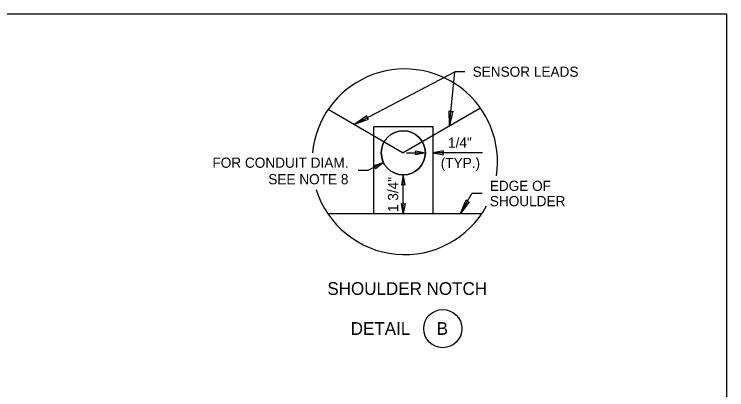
# Model space of a CAD drawing. Extents: x 99862 to 103151, y 100000 to 105076.
# Drawn here: x 102031 to 103151, y 104485 to 105076 of the extents above; entities that cross this region are included whole.
import ezdxf

# ---------------------------------------------------------------- set-up
doc = ezdxf.new("R2010")
doc.units = 0
for name, color, linetype in [('Level 1', 7, 'Continuous'), ('Level 15', 7, 'Continuous'), ('Level 18', 7, 'Continuous'), ('Level 20', 7, 'Continuous'), ('Level 22', 7, 'Continuous'), ('Level 33', 7, 'Continuous'), ('Level 60', 7, 'Continuous')]:
    doc.layers.add(name, color=color, linetype=linetype)

msp = doc.modelspace()

# ---------------------------------------------------------------- linework, layer by layer
at = {"layer": 'Level 1'}
msp.add_lwpolyline([(99862, 102999.5), (103151, 102999.5), (103151, 105075.5), (99862, 105075.5)], close=True, dxfattribs=at)
at = {"layer": 'Level 15'}
for p, q in [((102566.3, 104902.9), (102723.4, 104985.2)), ((102715.2, 104900.6), (102723.4, 104985.2)), ((102739.4, 104985.2), (102723.4, 104985.2)), ((102611.2, 104842.6), (102587.6, 104830.2)), ((102571.6, 104830.2), (102587.6, 104830.2)), ((102732.2, 104762.3), (102750.4, 104793.8)), ((102766.4, 104793.8), (102750.4, 104793.8))]:
    msp.add_line(p, q, dxfattribs=at)
for points in [[(102524.3, 104926.1), (102642.4, 104857.8)], [(102763.8, 104927.9), (102642.4, 104857.8)], [(102647.4, 104857.8), (102677.2, 104857.8)], [(102767.1, 104857.8), (102689.6, 104857.8)], [(102642.4, 104762.3), (102642.4, 104823.1)]]:
    msp.add_lwpolyline(points, dxfattribs=at)
for points in [[(102715.2, 104900.6), (102714.4, 104923.6), (102717.3, 104922.3), (102720.4, 104923)], [(102566.3, 104902.9), (102587.9, 104910.8), (102585.6, 104913), (102585.1, 104916.1)], [(102677.2, 104857.8), (102661.4, 104854.7), (102662.2, 104857.8), (102661.4, 104860.9)], [(102689.6, 104857.8), (102705.4, 104854.7), (102704.6, 104857.8), (102705.4, 104860.9)], [(102611.2, 104842.6), (102598.7, 104832.6), (102598, 104835.6), (102595.9, 104838)], [(102642.4, 104823.1), (102639.4, 104807.4), (102642.4, 104808.1), (102645.5, 104807.4)], [(102642.4, 104762.3), (102639.4, 104778), (102642.4, 104777.3), (102645.5, 104778)], [(102732.2, 104762.3), (102741, 104783.6), (102743.1, 104781.2), (102746.2, 104780.6)]]:
    msp.add_lwpolyline(points, close=True, dxfattribs=at)
at = {"layer": 'Level 18'}
msp.add_lwpolyline([(102595.3, 104762.3), (102689.6, 104762.3), (102689.6, 104898.4), (102595.3, 104898.4)], close=True, dxfattribs=at)
msp.add_circle((102642.4, 104857.8), 34.7, dxfattribs=at)
at = {"layer": 'Level 20'}
msp.add_circle((102704.5, 104581.4), 30, dxfattribs=at)
at = {"layer": 'Level 22'}
msp.add_line((102523.5, 104762.3), (102764.7, 104762.3), dxfattribs=at)
for start, end in [(351.3026, 174.5217), (197.4056, 331.7921)]:
    msp.add_arc((102644.7, 104843.6), 145.9, start, end, dxfattribs=at)
at = {"layer": 'Level 33'}
for start, end in [(0, 180), (180, 0)]:
    msp.add_arc((102642.4, 104857.8), 34.7, start, end, dxfattribs=at)
at = {"layer": 'Level 60'}
msp.add_line((103151, 105075.5), (103151, 105075.5), dxfattribs=at)

# ---------------------------------------------------------------- texts
at = {"layer": 'Level 20'}
for s, height, p in [('SENSOR LEADS', 16, (102751.4, 104977.2)), (' 1/4" ', 16, (102706.8, 104865.8)), ('(TYP.)', 16, (102701.3, 104833.8)), ('EDGE OF ', 16, (102778.4, 104797.8)), ('SHOULDER', 16, (102778.4, 104773.8)), ('SHOULDER NOTCH', 20, (102523, 104634.4)), ('DETAIL', 20, (102559.7, 104571.6)), ('B', 20, (102694.9, 104571.6))]:
    msp.add_text(s, height=height, dxfattribs=at).set_placement(p)
for s, rotation, p in [('FOR CONDUIT DIAM.', 360, (102342.3, 104834.2)), ('SEE NOTE 8', 360, (102430.1, 104808.2)), ('1 3/4"', 90, (102634.4, 104764.6))]:
    msp.add_text(s, height=16, rotation=rotation, dxfattribs=at).set_placement(p)

doc.saveas('drawing.dxf')
